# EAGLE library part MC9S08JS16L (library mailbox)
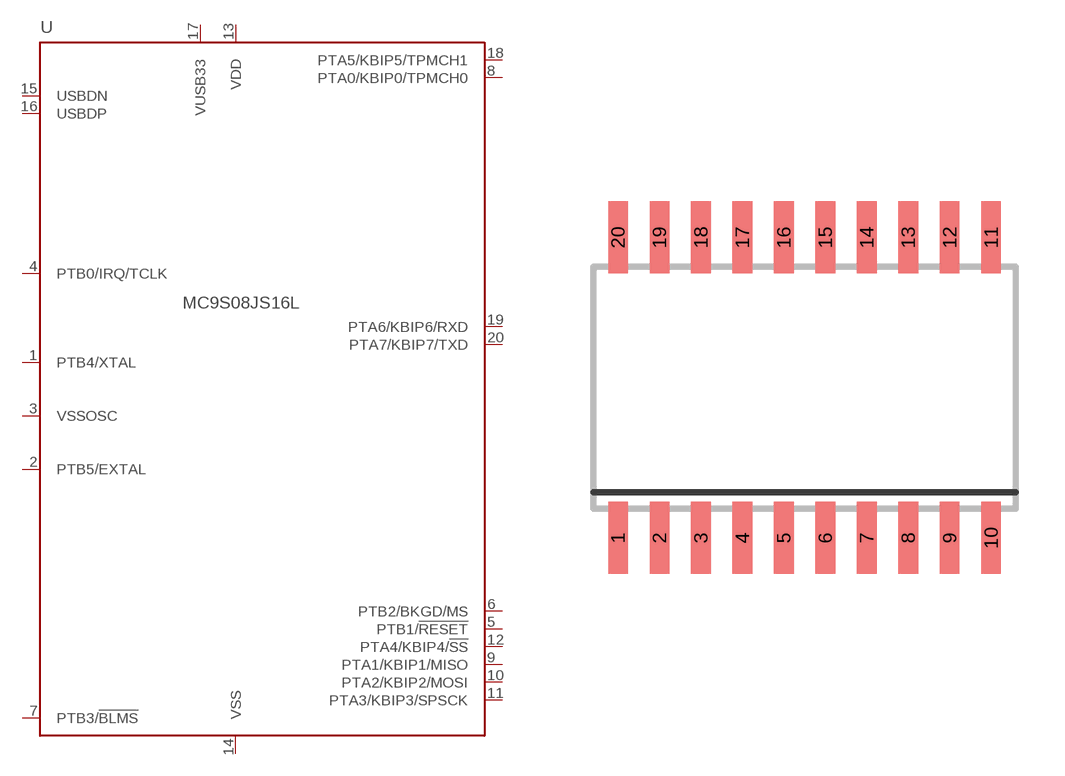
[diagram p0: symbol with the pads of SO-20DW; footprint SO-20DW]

Designator prefix -

## MC9S08JS16L  [SO-20DW]
1  PTB4/XTAL
2  PTB5/EXTAL
3  VSSOSC  pwr
4  PTB0/IRQ/TCLK  in
5  PTB1/!RESET
6  PTB2/BKGD/MS
7  PTB3/!BLMS
8  PTA0/KBIP0/TPMCH0
9  PTA1/KBIP1/MISO
10  PTA2/KBIP2/MOSI
11  PTA3/KBIP3/SPSCK
12  PTA4/KBIP4/!SS
13  VDD  pwr
14  VSS  pwr
15  USBDN
16  USBDP
17  VUSB33  pwr
18  PTA5/KBIP5/TPMCH1
19  PTA6/KBIP6/RXD
20  PTA7/KBIP7/TXD

## Footprint SO-20DW (pad centres in mm)
Small Outline Integrated Circuit wide
smd 0.6 x 2.2: 1 -5.715,-4.6; 2 -4.445,-4.6; 3 -3.175,-4.6; 4 -1.905,-4.6; 5 -0.635,-4.6; 6 0.635,-4.6; 7 1.905,-4.6; 8 3.175,-4.6; 9 4.445,-4.6; 10 5.715,-4.6; 11 5.715,4.6; 12 4.445,4.6; 13 3.175,4.6; 14 1.905,4.6; 15 0.635,4.6; 16 -0.635,4.6; 17 -1.905,4.6; 18 -3.175,4.6; 19 -4.445,4.6; 20 -5.715,4.6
